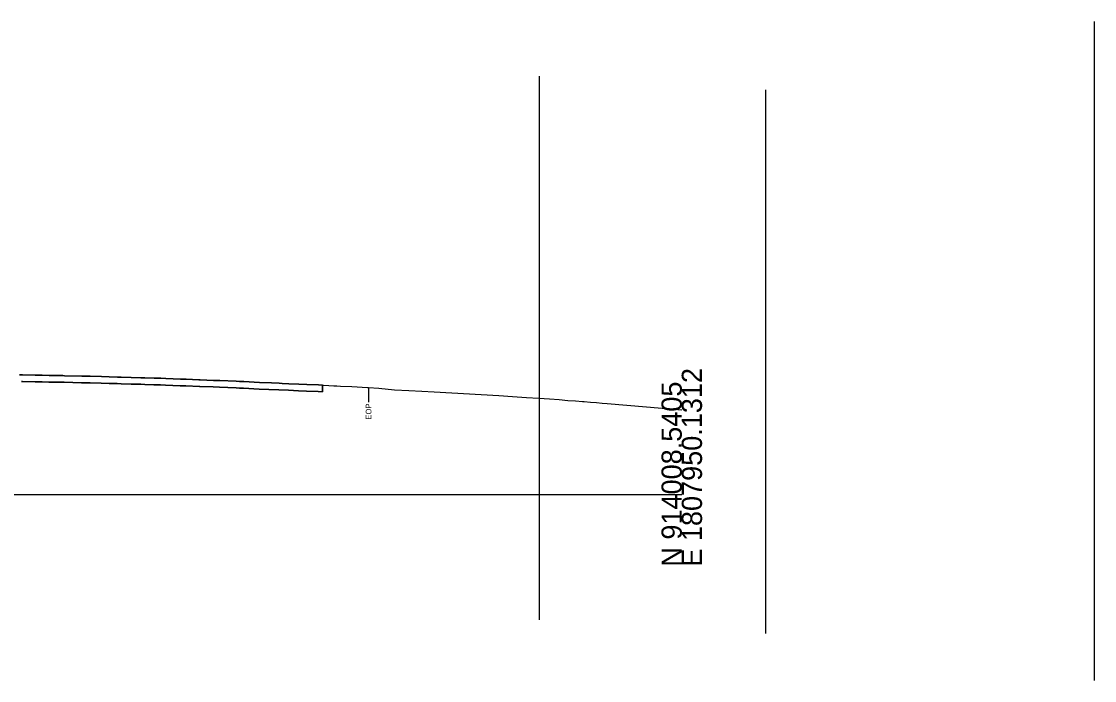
# Model space of a CAD drawing. Extents: x -26 to 1352, y -510 to 9596.
# Drawn here: x 208.6 to 357.1, y 1474.2 to 1565.4 of the extents above; entities that cross this region are included whole.
import ezdxf

# ---------------------------------------------------------------- set-up
doc = ezdxf.new("R2010")
doc.units = 0
for name, color, linetype in [('Exist Cross Section Cell', 7, 'Continuous'), ('Exist XS Ground Line', 7, 'Continuous'), ('Old_Level_10', 7, 'Continuous'), ('Prop XS Earthwork Shape', 7, 'Continuous'), ('Prop XS Exc Vertical Line 2', 7, 'Continuous'), ('Prop XS Exc Vertical Line 3', 7, 'Continuous'), ('Prop XS Exc Vertical Line 4', 7, 'Continuous'), ('Prop XS Finish Grade Pavement', 7, 'Continuous'), ('Prop XS Subgrade Earthwork', 7, 'Continuous')]:
    doc.layers.add(name, color=color, linetype=linetype)

msp = doc.modelspace()

# ---------------------------------------------------------------- linework, layer by layer
at = {"layer": 'Exist Cross Section Cell'}
msp.add_line((150, 1500), (300, 1500), dxfattribs=at)
at = {"layer": 'Exist XS Ground Line'}
msp.add_lwpolyline([(208.32, 1516.54), (208.62, 1516.54), (208.76, 1516.53), (210.53, 1516.51), (211.49, 1516.49), (212.42, 1516.47), (214.22, 1516.43), (214.32, 1516.43), (214.55, 1516.42), (216.95, 1516.37), (218.11, 1516.34), (219.68, 1516.3), (220.76, 1516.27), (221.9, 1516.24), (222.4, 1516.23), (223.8, 1516.19), (225.14, 1516.15), (225.7, 1516.14), (226.97, 1516.1), (227.88, 1516.07), (228.59, 1516.04), (230.61, 1515.96), (231.39, 1515.93), (233.17, 1515.87), (233.29, 1515.86), (233.34, 1515.86), (235.19, 1515.78), (236.07, 1515.74), (238.34, 1515.65), (238.8, 1515.63), (238.98, 1515.62), (239.39, 1515.6), (241.54, 1515.5), (243.22, 1515.42), (244.26, 1515.37), (244.67, 1515.35), (245.6, 1515.32), (246.99, 1515.26), (248.09, 1515.21), (249.73, 1515.14), (251.82, 1515.03), (252.27, 1515.01), (252.78, 1514.99), (254.33, 1514.91), (256.5, 1514.81), (256.55, 1514.8), (256.65, 1514.8), (258.07, 1514.7), (260.25, 1514.47), (262.23, 1514.39), (264.04, 1514.27), (265.71, 1514.17), (274.7, 1513.66), (276.59, 1513.53), (278.52, 1513.41), (280.2, 1513.3), (281.69, 1513.2), (283.02, 1513.11), (284.21, 1513), (285.28, 1512.93), (286.25, 1512.86), (286.48, 1512.84), (287.37, 1512.78), (288.19, 1512.7), (288.96, 1512.63), (289.68, 1512.58), (300, 1511.7)], dxfattribs=at)
at = {"layer": 'Old_Level_10'}
msp.add_line((256.65, 1514.8), (256.65, 1512.75), dxfattribs=at)
at = {"layer": 'Prop XS Earthwork Shape'}
for points in [[(208.6, 1515.62), (208.74, 1515.62), (210.51, 1515.59), (211.47, 1515.57), (212.4, 1515.55), (214.2, 1515.51), (214.3, 1515.51), (214.53, 1515.51), (216.92, 1515.45), (218.09, 1515.42), (219.65, 1515.38), (220.73, 1515.36), (221.87, 1515.33), (222.38, 1515.31), (223.77, 1515.27), (225.11, 1515.24), (225.67, 1515.22), (226.93, 1515.18), (227.84, 1515.15), (228.56, 1515.12), (230.57, 1515.04), (231.35, 1515.01), (233.26, 1514.95), (233.3, 1514.94), (235.15, 1514.87), (236.03, 1514.83), (238.3, 1514.73), (238.76, 1514.71), (238.94, 1514.7), (239.35, 1514.69), (241.49, 1514.58), (245.56, 1514.4), (246.95, 1514.35), (248.05, 1514.3), (249.68, 1514.22), (250.25, 1514.2), (250.25, 1515.11), (249.73, 1515.14), (248.09, 1515.21), (246.99, 1515.26), (245.6, 1515.32), (244.67, 1515.35), (244.26, 1515.37), (243.22, 1515.42), (241.54, 1515.5), (239.39, 1515.6), (238.98, 1515.62), (238.8, 1515.63), (238.34, 1515.65), (236.07, 1515.74), (235.19, 1515.78), (233.34, 1515.86), (233.29, 1515.86), (233.17, 1515.87), (231.39, 1515.93), (230.61, 1515.96), (228.59, 1516.04), (227.88, 1516.07), (226.97, 1516.1), (225.7, 1516.14), (225.14, 1516.15), (223.8, 1516.19), (222.4, 1516.23), (221.9, 1516.24), (220.76, 1516.27), (219.68, 1516.3), (218.11, 1516.34), (216.95, 1516.37), (214.55, 1516.42), (214.32, 1516.43), (214.22, 1516.43), (212.42, 1516.47), (211.49, 1516.49), (210.53, 1516.51), (208.76, 1516.53), (208.62, 1516.54), (208.32, 1516.54)], [(208.6, 1515.62), (208.74, 1515.62), (210.51, 1515.59), (211.47, 1515.57), (212.4, 1515.55), (214.2, 1515.51), (214.3, 1515.51), (214.53, 1515.51), (216.92, 1515.45), (218.09, 1515.42), (219.65, 1515.38), (220.73, 1515.36), (221.87, 1515.33), (222.38, 1515.31), (223.77, 1515.27), (225.11, 1515.24), (225.67, 1515.22), (226.93, 1515.18), (227.84, 1515.15), (228.56, 1515.12), (230.57, 1515.04), (231.35, 1515.01), (233.26, 1514.95), (233.3, 1514.94), (235.15, 1514.87), (236.03, 1514.83), (238.3, 1514.73), (238.76, 1514.71), (238.94, 1514.7), (239.35, 1514.69), (241.49, 1514.58), (245.56, 1514.4), (246.95, 1514.35), (248.05, 1514.3), (249.68, 1514.22), (250.25, 1514.2), (250.25, 1515.11), (249.73, 1515.14), (248.09, 1515.21), (246.99, 1515.26), (245.6, 1515.32), (244.67, 1515.35), (244.26, 1515.37), (243.22, 1515.42), (241.54, 1515.5), (239.39, 1515.6), (238.98, 1515.62), (238.8, 1515.63), (238.34, 1515.65), (236.07, 1515.74), (235.19, 1515.78), (233.34, 1515.86), (233.29, 1515.86), (233.17, 1515.87), (231.39, 1515.93), (230.61, 1515.96), (228.59, 1516.04), (227.88, 1516.07), (226.97, 1516.1), (225.7, 1516.14), (225.14, 1516.15), (223.8, 1516.19), (222.4, 1516.23), (221.9, 1516.24), (220.76, 1516.27), (219.68, 1516.3), (218.11, 1516.34), (216.95, 1516.37), (214.55, 1516.42), (214.32, 1516.43), (214.22, 1516.43), (212.42, 1516.47), (211.49, 1516.49), (210.53, 1516.51), (208.76, 1516.53), (208.62, 1516.54), (208.32, 1516.54)], [(208.32, 1516.54), (208.62, 1516.54), (208.76, 1516.53), (210.53, 1516.51), (211.49, 1516.49), (212.42, 1516.47), (214.22, 1516.43), (214.32, 1516.43), (214.55, 1516.42), (216.95, 1516.37), (218.11, 1516.34), (219.68, 1516.3), (220.76, 1516.27), (221.9, 1516.24), (222.4, 1516.23), (223.8, 1516.19), (225.14, 1516.15), (225.7, 1516.14), (226.97, 1516.1), (227.88, 1516.07), (228.59, 1516.04), (230.61, 1515.96), (231.39, 1515.93), (233.17, 1515.87), (233.29, 1515.86), (233.34, 1515.86), (235.19, 1515.78), (236.07, 1515.74), (238.34, 1515.65), (238.8, 1515.63), (238.98, 1515.62), (239.39, 1515.6), (241.54, 1515.5), (243.22, 1515.42), (244.26, 1515.37), (244.67, 1515.35), (245.6, 1515.32), (246.99, 1515.26), (248.09, 1515.21), (249.73, 1515.14), (250.25, 1515.11), (250.25, 1514.2), (249.68, 1514.22), (248.05, 1514.3), (246.95, 1514.35), (245.56, 1514.4), (241.49, 1514.58), (239.35, 1514.69), (238.94, 1514.7), (238.76, 1514.71), (238.3, 1514.73), (236.03, 1514.83), (235.15, 1514.87), (233.3, 1514.94), (233.26, 1514.95), (231.35, 1515.01), (230.57, 1515.04), (228.56, 1515.12), (227.84, 1515.15), (226.93, 1515.18), (225.67, 1515.22), (225.11, 1515.24), (223.77, 1515.27), (222.38, 1515.31), (221.87, 1515.33), (220.73, 1515.36), (219.65, 1515.38), (218.09, 1515.42), (216.92, 1515.45), (214.53, 1515.51), (214.3, 1515.51), (214.2, 1515.51), (212.4, 1515.55), (211.47, 1515.57), (210.51, 1515.59), (208.74, 1515.62), (208.6, 1515.62)], [(208.32, 1516.54), (208.62, 1516.54), (208.76, 1516.53), (210.53, 1516.51), (211.49, 1516.49), (212.42, 1516.47), (214.22, 1516.43), (214.32, 1516.43), (214.55, 1516.42), (216.95, 1516.37), (218.11, 1516.34), (219.68, 1516.3), (220.76, 1516.27), (221.9, 1516.24), (222.4, 1516.23), (223.8, 1516.19), (225.14, 1516.15), (225.7, 1516.14), (226.97, 1516.1), (227.88, 1516.07), (228.59, 1516.04), (230.61, 1515.96), (231.39, 1515.93), (233.17, 1515.87), (233.29, 1515.86), (233.34, 1515.86), (235.19, 1515.78), (236.07, 1515.74), (238.34, 1515.65), (238.8, 1515.63), (238.98, 1515.62), (239.39, 1515.6), (241.54, 1515.5), (243.22, 1515.42), (244.26, 1515.37), (244.67, 1515.35), (245.6, 1515.32), (246.99, 1515.26), (248.09, 1515.21), (249.73, 1515.14), (250.25, 1515.11), (250.25, 1514.2), (249.68, 1514.22), (248.05, 1514.3), (246.95, 1514.35), (245.56, 1514.4), (241.49, 1514.58), (239.35, 1514.69), (238.94, 1514.7), (238.76, 1514.71), (238.3, 1514.73), (236.03, 1514.83), (235.15, 1514.87), (233.3, 1514.94), (233.26, 1514.95), (231.35, 1515.01), (230.57, 1515.04), (228.56, 1515.12), (227.84, 1515.15), (226.93, 1515.18), (225.67, 1515.22), (225.11, 1515.24), (223.77, 1515.27), (222.38, 1515.31), (221.87, 1515.33), (220.73, 1515.36), (219.65, 1515.38), (218.09, 1515.42), (216.92, 1515.45), (214.53, 1515.51), (214.3, 1515.51), (214.2, 1515.51), (212.4, 1515.55), (211.47, 1515.57), (210.51, 1515.59), (208.74, 1515.62), (208.6, 1515.62)]]:
    msp.add_lwpolyline(points, dxfattribs=at)
at = {"layer": 'Prop XS Exc Vertical Line 2'}
msp.add_line((280.32, 1482.63), (280.32, 1557.87), dxfattribs=at)
at = {"layer": 'Prop XS Exc Vertical Line 3'}
msp.add_line((311.65, 1480.76), (311.65, 1555.99), dxfattribs=at)
at = {"layer": 'Prop XS Exc Vertical Line 4'}
msp.add_line((357.13, 1474.24), (357.13, 1565.44), dxfattribs=at)
at = {"layer": 'Prop XS Finish Grade Pavement'}
msp.add_lwpolyline([(208.32, 1516.54), (208.62, 1516.54), (208.76, 1516.53), (210.52, 1516.51), (211.48, 1516.49), (212.42, 1516.47), (214.22, 1516.43), (214.32, 1516.43), (214.55, 1516.42), (216.95, 1516.37), (218.11, 1516.34), (219.68, 1516.3), (220.75, 1516.27), (221.9, 1516.24), (222.4, 1516.23), (223.8, 1516.19), (225.14, 1516.15), (225.7, 1516.14), (226.96, 1516.1), (227.88, 1516.07), (228.59, 1516.04), (230.6, 1515.96), (231.39, 1515.93), (233.17, 1515.87), (233.29, 1515.86), (233.34, 1515.86), (235.19, 1515.78), (236.07, 1515.74), (238.34, 1515.65), (238.8, 1515.63), (238.98, 1515.62), (239.39, 1515.6), (241.54, 1515.5), (243.22, 1515.42), (244.26, 1515.38), (244.67, 1515.36), (245.6, 1515.32), (246.99, 1515.26), (248.09, 1515.21), (249.73, 1515.14), (250.25, 1515.11)], dxfattribs=at)
at = {"layer": 'Prop XS Subgrade Earthwork'}
for p, q in [((208.61, 1515.62), (208.74, 1515.62)), ((228.56, 1515.12), (230.57, 1515.04)), ((230.57, 1515.04), (231.35, 1515.01)), ((250.25, 1514.2), (250.25, 1515.11)), ((231.36, 1515.01), (231.36, 1515.01)), ((231.36, 1515.01), (233.26, 1514.95)), ((233.26, 1514.95), (233.26, 1514.95)), ((241.49, 1514.58), (245.56, 1514.4)), ((245.56, 1514.4), (246.95, 1514.35)), ((245.56, 1514.4), (245.56, 1514.4)), ((246.95, 1514.35), (248.05, 1514.3)), ((248.05, 1514.3), (249.68, 1514.22)), ((249.68, 1514.22), (250.25, 1514.2)), ((250.2, 1514.2), (250.2, 1514.2))]:
    msp.add_line(p, q, dxfattribs=at)
for points in [[(208.74, 1515.62), (210.51, 1515.59), (211.47, 1515.57)], [(211.47, 1515.57), (212.4, 1515.55), (214.2, 1515.51)], [(214.2, 1515.51), (214.3, 1515.51), (214.53, 1515.51), (216.92, 1515.45), (218.09, 1515.42), (219.65, 1515.38)], [(219.66, 1515.38), (220.73, 1515.36), (221.87, 1515.33), (222.38, 1515.31), (223.77, 1515.27)], [(223.77, 1515.27), (225.11, 1515.24), (225.67, 1515.22)], [(225.67, 1515.22), (226.93, 1515.18), (227.84, 1515.15), (228.56, 1515.12)], [(233.26, 1514.95), (233.3, 1514.94), (235.15, 1514.87)], [(235.15, 1514.87), (236.03, 1514.83), (238.3, 1514.73), (238.76, 1514.71), (238.94, 1514.7)], [(238.94, 1514.7), (239.35, 1514.69), (241.49, 1514.58)]]:
    msp.add_lwpolyline(points, dxfattribs=at)
for centre, start, end in [((208.62, 1516.54), 268.8036, 269.0516), ((208.76, 1516.53), 269.0516, 269.0809), ((211.48, 1516.49), 268.8056, 268.9056), ((214.22, 1516.43), 268.7698, 268.9161), ((219.68, 1516.3), 268.4645, 268.6368), ((223.8, 1516.19), 268.4037, 268.4287), ((225.7, 1516.14), 268.2718, 268.3227), ((228.59, 1516.04), 267.7282, 267.7399), ((230.6, 1515.96), 267.7399, 267.7471), ((231.39, 1515.93), 267.7471, 267.9646), ((235.19, 1515.78), 267.5651, 267.635), ((238.98, 1515.62), 267.4462, 267.5244), ((241.54, 1515.5), 267.1995, 267.5139)]:
    msp.add_arc(centre, 0.917, start, end, dxfattribs=at)

# ---------------------------------------------------------------- texts
at = {"layer": 'Exist Cross Section Cell'}
for s, p in [('E 1807950.1312', (302.8, 1490)), ('N 914008.5405', (300, 1490))]:
    msp.add_text(s, height=2.8, rotation=90, dxfattribs=at).set_placement(p)
at = {"layer": 'Old_Level_10'}
msp.add_text('EOP', height=0.787, rotation=90, dxfattribs=at).set_placement((257.04, 1510.35))

doc.saveas('drawing.dxf')
